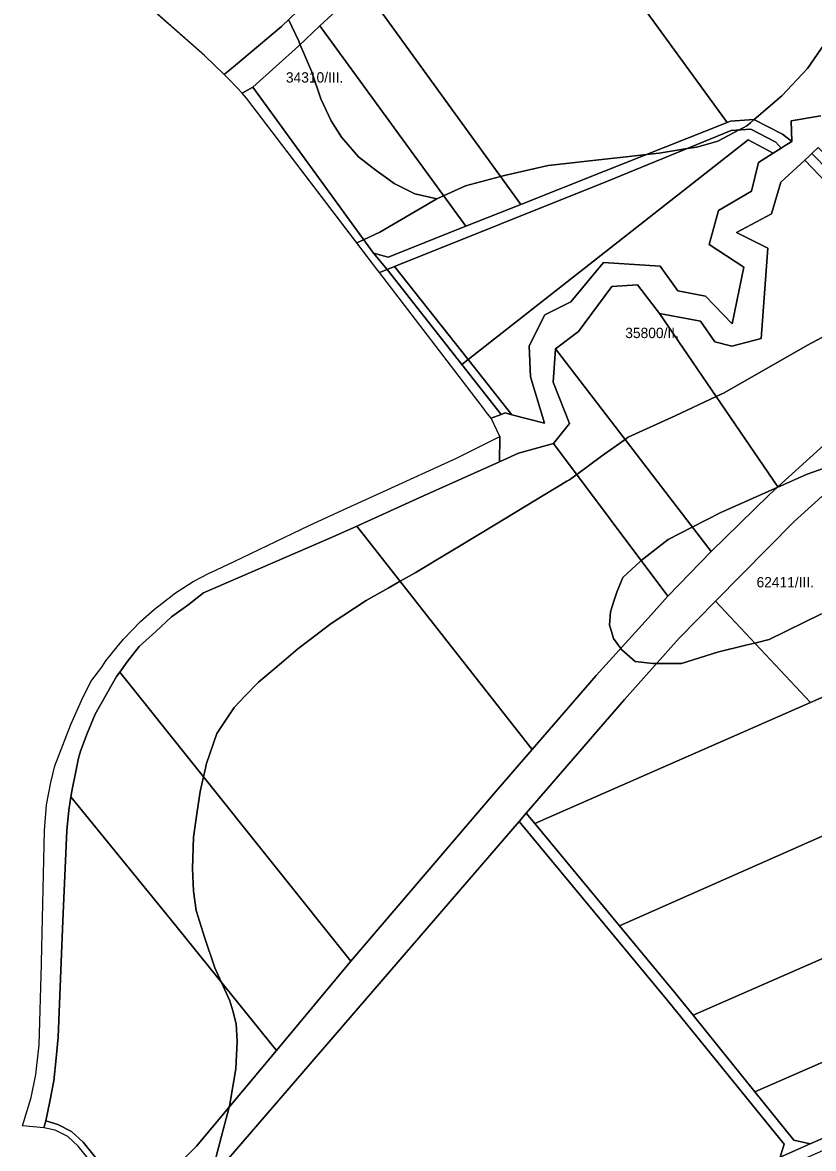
# Model space of a CAD drawing. Extents: x -522079 to -518833, y -1142400 to -1139961.
# Drawn here: x -521980 to -521596, y -1141010 to -1140463 of the extents above; entities that cross this region are included whole.
import ezdxf

# ---------------------------------------------------------------- set-up
doc = ezdxf.new("R2010")
doc.units = 0
for name, color, linetype in [('95560013', 7, 'Continuous'), ('95630013', 7, 'Continuous'), ('95640013', 7, 'Continuous'), ('95660013', 7, 'Continuous')]:
    doc.layers.add(name, color=color, linetype=linetype)

msp = doc.modelspace()

# ---------------------------------------------------------------- linework, layer by layer
at = {"layer": '95560013'}
for points in [[(-521592.51, -1140508.64), (-521606.9, -1140511.13), (-521606.6, -1140521.1), (-521611.18, -1140517.57), (-521625.07, -1140510.37), (-521636.41, -1140511.21), (-521638.02, -1140511.86), (-521742.3, -1140368.5), (-521728.93, -1140357.06), (-521708.67, -1140341.98), (-521697.12, -1140332.11), (-521688.85, -1140323.27), (-521680.22, -1140314.66), (-521674.58, -1140306.67), (-521664.44, -1140291.34), (-521641.46, -1140251.62), (-521633.25, -1140239.25), (-521625.36, -1140230.13), (-521613.09, -1140218.9), (-521610.22, -1140216.5), (-521608.33, -1140219.87), (-521596.95, -1140234.61), (-521579.62, -1140257.92)], [(-521925.13, -1141037.95), (-521895.5, -1141008.4), (-521856.78, -1140962.03), (-521820.63, -1140918.73), (-521750.36, -1140836.58), (-521732.61, -1140815.99), (-521701.61, -1140780.11), (-521674.73, -1140750.53), (-521666.78, -1140741.6), (-521645.77, -1140720.02), (-521617.82, -1140692.69), (-521613.36, -1140688.64), (-521587.52, -1140665.2)], [(-521576.52, -1140679.31), (-521605.53, -1140705.44), (-521643.56, -1140744), (-521661.3, -1140761.99), (-521687.87, -1140791.7), (-521735.53, -1140846.95), (-521738.91, -1140850.87), (-521884.07, -1141019.15)]]:
    msp.add_lwpolyline(points, dxfattribs=at)
for points in [[(-521924.65, -1140450.32), (-521818.63, -1140351.09), (-521781.95, -1140390.97), (-521803.88, -1140414.74), (-521822.79, -1140434.86), (-521839, -1140450.48), (-521854.3, -1140465.27), (-521876.66, -1140484.09), (-521882.18, -1140488.56), (-521891.73, -1140479.43)], [(-521747.91, -1140373.33), (-521742.3, -1140368.5), (-521638.02, -1140511.86), (-521697.45, -1140535.57), (-521738.18, -1140551.68), (-521815.4, -1140444.86), (-521814.39, -1140443.83), (-521794.87, -1140423.48), (-521773.82, -1140399.6), (-521757.78, -1140381.98)], [(-521829.77, -1140459.58), (-521815.4, -1140444.86), (-521738.18, -1140551.68), (-521764.87, -1140562.24), (-521835.62, -1140465.09)], [(-521835.62, -1140465.09), (-521764.87, -1140562.24), (-521802.53, -1140577.14), (-521809.71, -1140575.34), (-521868.24, -1140494.75), (-521845.84, -1140474.71)], [(-521809.71, -1140575.34), (-521803.08, -1140583.22), (-521806.71, -1140584.66), (-521807.95, -1140583.04), (-521871.3, -1140500.06), (-521873.47, -1140497.6), (-521868.24, -1140494.75)], [(-521802.53, -1140577.14), (-521764.87, -1140562.24), (-521738.18, -1140551.68), (-521697.45, -1140535.57), (-521638.02, -1140511.86), (-521636.41, -1140511.21), (-521625.07, -1140510.37), (-521611.18, -1140517.57), (-521606.6, -1140521.1), (-521609.78, -1140523.1), (-521611.69, -1140524.3), (-521614.4, -1140521.49), (-521626.56, -1140515.18), (-521635.99, -1140515.78), (-521696.07, -1140540.42), (-521799.46, -1140581.76), (-521803.08, -1140583.22), (-521809.71, -1140575.34)], [(-521614.4, -1140521.49), (-521611.69, -1140524.3), (-521615.57, -1140526.74), (-521627.73, -1140520.35), (-521763.73, -1140626.86), (-521799.46, -1140581.76), (-521696.07, -1140540.42), (-521635.99, -1140515.78), (-521626.56, -1140515.18)], [(-521646.65, -1140571), (-521629.87, -1140582.04), (-521635.54, -1140609.6), (-521648.43, -1140596.09), (-521661.89, -1140593.5), (-521670.5, -1140581.53), (-521698, -1140579.74), (-521713.89, -1140598.84), (-521726.52, -1140605.2), (-521734.01, -1140620.28), (-521733.38, -1140635.33), (-521726.67, -1140657.74), (-521742.5, -1140653.65), (-521763.73, -1140626.86), (-521627.73, -1140520.35), (-521615.57, -1140526.74), (-521622.75, -1140531.26), (-521626.2, -1140545.21), (-521642.26, -1140554.66)], [(-521521.75, -1140612.22), (-521600.31, -1140530.11), (-521598.04, -1140528.01), (-521596.8, -1140526.87), (-521570.34, -1140553.98), (-521517.85, -1140609.14)], [(-521587.52, -1140665.2), (-521613.36, -1140688.64), (-521670.89, -1140604.59), (-521650.96, -1140608.19), (-521643.99, -1140618.34), (-521635.78, -1140620.38), (-521621.47, -1140616.67), (-521618.3, -1140572.85), (-521633.5, -1140565.29), (-521616.47, -1140556.14), (-521611.96, -1140540.86), (-521600.31, -1140530.11), (-521521.75, -1140612.22), (-521556.8, -1140639.91)], [(-521799.46, -1140581.76), (-521763.73, -1140626.86), (-521766.84, -1140629.25), (-521803.08, -1140583.22)], [(-521806.71, -1140584.66), (-521803.08, -1140583.22), (-521766.84, -1140629.25), (-521747.72, -1140653.54), (-521752.49, -1140655.36), (-521754.23, -1140653.26), (-521756.45, -1140650.36)], [(-521613.36, -1140688.64), (-521617.82, -1140692.69), (-521645.77, -1140720.02), (-521721.28, -1140621.72), (-521710.1, -1140613.29), (-521693.94, -1140591.41), (-521681.44, -1140590.68), (-521670.89, -1140604.59)], [(-521714.47, -1140657.84), (-521722.39, -1140637.91), (-521721.28, -1140621.72), (-521645.77, -1140720.02), (-521666.78, -1140741.6), (-521722.24, -1140667.6)], [(-521424.45, -1140717.21), (-521517.19, -1140758), (-521597.52, -1140793.25), (-521643.56, -1140744), (-521605.53, -1140705.44), (-521576.52, -1140679.31), (-521545.43, -1140654.05), (-521509.24, -1140625.15)], [(-521763.73, -1140626.86), (-521742.5, -1140653.65), (-521745.77, -1140652.8), (-521747.72, -1140653.54), (-521766.84, -1140629.25)], [(-521674.73, -1140750.53), (-521701.61, -1140780.11), (-521732.61, -1140815.99), (-521817.76, -1140707.64), (-521785.36, -1140693.05), (-521748.53, -1140676.5), (-521739.27, -1140672.34), (-521722.24, -1140667.6), (-521666.78, -1140741.6)], [(-521820.63, -1140918.73), (-521932.78, -1140778.46), (-521929.14, -1140773.45), (-521923.36, -1140766.09), (-521915.35, -1140758.73), (-521907.65, -1140751.59), (-521899.73, -1140746), (-521892.09, -1140739.95), (-521829.78, -1140713), (-521817.76, -1140707.64), (-521732.61, -1140815.99), (-521750.36, -1140836.58)], [(-521589.34, -1140856.91), (-521690.16, -1140901.59), (-521731.35, -1140851.98), (-521597.52, -1140793.25), (-521517.19, -1140758), (-521424.45, -1140717.21), (-521383.31, -1140761.88), (-521381.12, -1140763.92), (-521473.38, -1140805.12)], [(-521735.53, -1140846.95), (-521687.87, -1140791.7), (-521661.3, -1140761.99), (-521643.56, -1140744), (-521597.52, -1140793.25), (-521731.35, -1140851.98)], [(-521589.34, -1140856.91), (-521473.38, -1140805.12), (-521381.12, -1140763.92), (-521343.03, -1140805.79), (-521433.97, -1140848.31), (-521555.85, -1140901.74), (-521654.5, -1140944.84), (-521662.84, -1140934.49), (-521690.16, -1140901.59)], [(-521856.78, -1140962.03), (-521908.14, -1140898.33), (-521956.51, -1140838.94), (-521956.06, -1140836.18), (-521953.99, -1140825.94), (-521952.78, -1140820.25), (-521951.85, -1140816.81), (-521948.6, -1140808.27), (-521944.68, -1140798.86), (-521939.28, -1140789.17), (-521934.35, -1140780.63), (-521932.78, -1140778.46), (-521820.63, -1140918.73)], [(-521343.03, -1140805.79), (-521311.05, -1140836.96), (-521307.59, -1140840.17), (-521401.58, -1140884.75), (-521526.28, -1140939.14), (-521624.6, -1140981.98), (-521654.5, -1140944.84), (-521555.85, -1140901.74), (-521433.97, -1140848.31)], [(-521968.74, -1140996.16), (-521966.75, -1140986.81), (-521964.79, -1140976.78), (-521963.61, -1140965.78), (-521962.64, -1140955.52), (-521961.27, -1140919.13), (-521960.41, -1140899.15), (-521958.48, -1140855.25), (-521957.55, -1140845.37), (-521956.51, -1140838.94), (-521908.14, -1140898.33), (-521856.78, -1140962.03), (-521895.5, -1141008.4), (-521925.13, -1141037.95), (-521927.04, -1141035.61), (-521950.59, -1141006.47), (-521956.25, -1141001.25), (-521962.85, -1140997.93)], [(-521526.28, -1140939.14), (-521401.58, -1140884.75), (-521307.59, -1140840.17), (-521288.46, -1140863.02), (-521289.17, -1140869.28), (-521455.15, -1140944.86), (-521597.65, -1141007.23), (-521605.69, -1141005.48), (-521624.6, -1140981.98)], [(-521690.16, -1140901.59), (-521662.84, -1140934.49), (-521654.5, -1140944.84), (-521624.6, -1140981.98), (-521605.69, -1141005.48), (-521597.65, -1141007.23), (-521612.22, -1141013.76), (-521610.31, -1141007.37), (-521666.76, -1140937.87), (-521738.91, -1140850.87), (-521735.53, -1140846.95), (-521731.35, -1140851.98)], [(-521666.76, -1140937.87), (-521610.31, -1141007.37), (-521612.22, -1141013.76), (-521737.51, -1141069.87), (-521813.35, -1141102.46), (-521884.07, -1141019.15), (-521738.91, -1140850.87)], [(-521288.46, -1140863.02), (-521283.24, -1140866.3), (-521272.67, -1140872.95), (-521285.04, -1140873.12), (-521453.3, -1140949.4), (-521594.31, -1141011.83), (-521607.81, -1141017.81), (-521735.67, -1141074.42), (-521844.44, -1141121.41), (-521845.59, -1141127.96), (-521855.85, -1141115.33), (-521847.83, -1141117.27), (-521813.35, -1141102.46), (-521737.51, -1141069.87), (-521612.22, -1141013.76), (-521597.65, -1141007.23), (-521455.15, -1140944.86), (-521289.17, -1140869.28)]]:
    msp.add_lwpolyline(points, close=True, dxfattribs=at)
at = {"layer": '95630013'}
for points in [[(-521593.79, -1140524.1), (-521596.8, -1140526.87), (-521598.04, -1140528.01), (-521600.31, -1140530.11), (-521611.96, -1140540.86), (-521616.47, -1140556.14), (-521633.5, -1140565.29), (-521618.3, -1140572.85), (-521621.47, -1140616.67), (-521635.78, -1140620.38), (-521643.99, -1140618.34), (-521650.96, -1140608.19), (-521670.89, -1140604.59), (-521681.44, -1140590.68), (-521693.94, -1140591.41), (-521710.1, -1140613.29), (-521721.28, -1140621.72), (-521722.39, -1140637.91), (-521714.47, -1140657.84), (-521722.24, -1140667.6), (-521739.27, -1140672.34), (-521748.53, -1140676.5), (-521748.38, -1140664.24), (-521752.49, -1140655.36), (-521747.72, -1140653.54), (-521745.77, -1140652.8), (-521742.5, -1140653.65), (-521726.67, -1140657.74), (-521733.38, -1140635.33), (-521734.01, -1140620.28), (-521726.52, -1140605.2), (-521713.89, -1140598.84), (-521698, -1140579.74), (-521670.5, -1140581.53), (-521661.89, -1140593.5), (-521648.43, -1140596.09), (-521635.54, -1140609.6), (-521629.87, -1140582.04), (-521646.65, -1140571), (-521642.26, -1140554.66), (-521626.2, -1140545.21), (-521622.75, -1140531.26), (-521615.57, -1140526.74), (-521611.69, -1140524.3), (-521609.78, -1140523.1), (-521606.6, -1140521.1), (-521606.9, -1140511.13), (-521592.51, -1140508.64)], [(-521929.14, -1141037.67), (-521952.92, -1141008.37), (-521958.05, -1141003.66), (-521964.16, -1141000.63), (-521969.71, -1140999.55), (-521968.74, -1140996.16), (-521962.85, -1140997.93), (-521956.25, -1141001.25), (-521950.59, -1141006.47), (-521927.04, -1141035.61)]]:
    msp.add_lwpolyline(points, dxfattribs=at)
for points in [[(-521513.48, -1140605.69), (-521517.85, -1140609.14), (-521570.34, -1140553.98), (-521596.8, -1140526.87), (-521593.79, -1140524.1), (-521584.91, -1140532.83), (-521566.82, -1140550.59)], [(-521968.74, -1140996.16), (-521969.71, -1140999.55), (-521980.02, -1140998.54), (-521975.77, -1140984.83), (-521973.56, -1140973.69), (-521972.01, -1140959.19), (-521970.73, -1140920.13), (-521970.78, -1140919.37), (-521969.35, -1140855.23), (-521968.4, -1140842.82), (-521966.23, -1140832.06), (-521964.35, -1140823.92), (-521960.5, -1140813.97), (-521956.64, -1140803.89), (-521951.34, -1140792.2), (-521946.81, -1140782.96), (-521941.53, -1140776.07), (-521939.58, -1140773.02), (-521933.99, -1140766.2), (-521930.99, -1140762.54), (-521922.69, -1140753.87), (-521915.99, -1140747.92), (-521907.36, -1140741.3), (-521906.16, -1140740.38), (-521897.11, -1140734.61), (-521889.34, -1140730.49), (-521885.86, -1140728.85), (-521877.29, -1140724.81), (-521840.82, -1140707.39), (-521822.52, -1140699.01), (-521804.78, -1140690.88), (-521769.34, -1140674.65), (-521748.38, -1140664.24), (-521748.53, -1140676.5), (-521785.36, -1140693.05), (-521817.76, -1140707.64), (-521829.78, -1140713), (-521892.09, -1140739.95), (-521899.73, -1140746), (-521907.65, -1140751.59), (-521915.35, -1140758.73), (-521923.36, -1140766.09), (-521929.14, -1140773.45), (-521932.78, -1140778.46), (-521934.35, -1140780.63), (-521939.28, -1140789.17), (-521944.68, -1140798.86), (-521948.6, -1140808.27), (-521951.85, -1140816.81), (-521952.78, -1140820.25), (-521953.99, -1140825.94), (-521956.06, -1140836.18), (-521956.51, -1140838.94), (-521957.55, -1140845.37), (-521958.48, -1140855.25), (-521960.41, -1140899.15), (-521961.27, -1140919.13), (-521962.64, -1140955.52), (-521963.61, -1140965.78), (-521964.79, -1140976.78), (-521966.75, -1140986.81)]]:
    msp.add_lwpolyline(points, close=True, dxfattribs=at)
at = {"layer": '95640013'}
msp.add_lwpolyline([(-521829.77, -1140459.58), (-521835.62, -1140465.09), (-521845.84, -1140474.71), (-521868.24, -1140494.75), (-521873.47, -1140497.6), (-521875.9, -1140495.08), (-521879.74, -1140491.09), (-521882.18, -1140488.56), (-521876.66, -1140484.09), (-521854.3, -1140465.27), (-521839, -1140450.48)], dxfattribs=at)
at = {"layer": '95660013'}
for points in [[(-521850.83, -1140461.92), (-521845.96, -1140472.52), (-521845.26, -1140474.16), (-521843.12, -1140479.15), (-521839.74, -1140487.06), (-521835.19, -1140500.35), (-521830.22, -1140511.15), (-521825.25, -1140519.04), (-521816.97, -1140528.6), (-521808.28, -1140535.24), (-521802.62, -1140539.29), (-521799.58, -1140541.47), (-521789.65, -1140546.45), (-521778.88, -1140548.95), (-521806.62, -1140565.15), (-521814.45, -1140568.81), (-521817.66, -1140570.32), (-521871.3, -1140500.06), (-521873.47, -1140497.6), (-521875.9, -1140495.08), (-521879.74, -1140491.09), (-521882.18, -1140488.56), (-521891.73, -1140479.43), (-521924.23, -1140450.69)], [(-521589.25, -1140471.59), (-521598.91, -1140485.69), (-521611.51, -1140498.91), (-521624.87, -1140510.47), (-521626.68, -1140512.03), (-521628.5, -1140513.6), (-521630.26, -1140514.52), (-521632.2, -1140515.54), (-521642.55, -1140520.95), (-521651.63, -1140523.59), (-521652.89, -1140523.8), (-521657.38, -1140524.55), (-521670.97, -1140526.82), (-521677.18, -1140527.48), (-521687.01, -1140528.53), (-521695.86, -1140529.47), (-521724.86, -1140532.7), (-521745.36, -1140537.4), (-521747.99, -1140538.11), (-521764.98, -1140542.69), (-521775.62, -1140547.48), (-521778.88, -1140548.95), (-521789.65, -1140546.45), (-521799.58, -1140541.47), (-521802.62, -1140539.29), (-521808.28, -1140535.24), (-521816.97, -1140528.6), (-521825.25, -1140519.04), (-521830.22, -1140511.15), (-521835.19, -1140500.35), (-521839.74, -1140487.06), (-521843.12, -1140479.15), (-521845.26, -1140474.16), (-521845.96, -1140472.52), (-521850.83, -1140461.92)], [(-521929.14, -1141037.67), (-521952.92, -1141008.37), (-521958.05, -1141003.66), (-521964.16, -1141000.63), (-521969.71, -1140999.55), (-521980.02, -1140998.54), (-521975.77, -1140984.83), (-521973.56, -1140973.69), (-521972.01, -1140959.19), (-521970.73, -1140920.13), (-521970.78, -1140919.37), (-521969.35, -1140855.23), (-521968.4, -1140842.82), (-521966.23, -1140832.06), (-521964.35, -1140823.92), (-521960.5, -1140813.97), (-521956.64, -1140803.89), (-521951.34, -1140792.2), (-521946.81, -1140782.96), (-521941.53, -1140776.07), (-521939.58, -1140773.02), (-521933.99, -1140766.2), (-521930.99, -1140762.54), (-521922.69, -1140753.87), (-521915.99, -1140747.92), (-521907.36, -1140741.3), (-521906.16, -1140740.38), (-521897.11, -1140734.61), (-521889.34, -1140730.49), (-521885.86, -1140728.85), (-521877.29, -1140724.81), (-521840.82, -1140707.39), (-521822.52, -1140699.01), (-521804.78, -1140690.88), (-521769.34, -1140674.65), (-521748.38, -1140664.24), (-521752.49, -1140655.36), (-521754.23, -1140653.26), (-521756.45, -1140650.36), (-521806.71, -1140584.66), (-521807.95, -1140583.04), (-521817.66, -1140570.32), (-521814.45, -1140568.81), (-521806.62, -1140565.15), (-521778.88, -1140548.95), (-521775.62, -1140547.48), (-521764.98, -1140542.69), (-521747.99, -1140538.11), (-521745.36, -1140537.4), (-521724.86, -1140532.7), (-521695.86, -1140529.47), (-521687.01, -1140528.53), (-521677.18, -1140527.48), (-521670.97, -1140526.82), (-521657.38, -1140524.55), (-521652.89, -1140523.8), (-521651.63, -1140523.59), (-521642.55, -1140520.95), (-521632.2, -1140515.54), (-521630.26, -1140514.52), (-521628.5, -1140513.6), (-521626.68, -1140512.03), (-521624.87, -1140510.47), (-521611.51, -1140498.91), (-521598.91, -1140485.69), (-521589.25, -1140471.59)], [(-521575.67, -1140607.49), (-521598.95, -1140619.93), (-521639.43, -1140643.03), (-521641.26, -1140643.88), (-521643.33, -1140644.85), (-521663.22, -1140654.19), (-521685.99, -1140664.6), (-521687.51, -1140665.68), (-521698.9, -1140673.74), (-521711, -1140682.59), (-521713.82, -1140684.66), (-521714.9, -1140685.31), (-521715.85, -1140685.88), (-521756.08, -1140710.29), (-521789.48, -1140730.34), (-521796.7, -1140734.43), (-521802.6, -1140737.76), (-521813.26, -1140743.79), (-521830.22, -1140754.96), (-521841.02, -1140763.09), (-521846.41, -1140767.15), (-521854.34, -1140773.94), (-521865.39, -1140783.39), (-521872.05, -1140790.21), (-521877.28, -1140795.58), (-521885.63, -1140808.26), (-521890.69, -1140822.73), (-521890.84, -1140823.43), (-521891.19, -1140825.02), (-521892.14, -1140829.28), (-521893.73, -1140836.44), (-521895.32, -1140847.16), (-521897.01, -1140858.52), (-521897.52, -1140873.75), (-521897.01, -1140884.67), (-521895.75, -1140894.06), (-521891.7, -1140907), (-521886.64, -1140921.98), (-521883.43, -1140928.98), (-521879.3, -1140937.97), (-521877.98, -1140942.83), (-521876.27, -1140949.14), (-521875.76, -1140957.51), (-521876.52, -1140970.97), (-521879.3, -1140987.98), (-521879.69, -1140989.47), (-521883.38, -1141003.58), (-521886.14, -1141014.12)], [(-521886.14, -1141014.12), (-521883.38, -1141003.58), (-521879.69, -1140989.47), (-521879.3, -1140987.98), (-521876.52, -1140970.97), (-521875.76, -1140957.51), (-521876.27, -1140949.14), (-521877.98, -1140942.83), (-521879.3, -1140937.97), (-521883.43, -1140928.98), (-521886.64, -1140921.98), (-521891.7, -1140907), (-521895.75, -1140894.06), (-521897.01, -1140884.67), (-521897.52, -1140873.75), (-521897.01, -1140858.52), (-521895.32, -1140847.16), (-521893.73, -1140836.44), (-521892.14, -1140829.28), (-521891.19, -1140825.02), (-521890.84, -1140823.43), (-521890.69, -1140822.73), (-521885.63, -1140808.26), (-521877.28, -1140795.58), (-521872.05, -1140790.21), (-521865.39, -1140783.39), (-521854.34, -1140773.94), (-521846.41, -1140767.15), (-521841.02, -1140763.09), (-521830.22, -1140754.96), (-521813.26, -1140743.79), (-521802.6, -1140737.76), (-521796.7, -1140734.43), (-521789.48, -1140730.34), (-521756.08, -1140710.29), (-521715.85, -1140685.88), (-521714.9, -1140685.31), (-521713.82, -1140684.66), (-521711, -1140682.59), (-521698.9, -1140673.74), (-521687.51, -1140665.68), (-521685.99, -1140664.6), (-521663.22, -1140654.19), (-521643.33, -1140644.85), (-521641.26, -1140643.88), (-521639.43, -1140643.03), (-521598.95, -1140619.93), (-521575.67, -1140607.49)], [(-521592.12, -1140750.19), (-521617.61, -1140762.73), (-521624.5, -1140764.38), (-521628.89, -1140765.44), (-521642.6, -1140768.75), (-521660.09, -1140774.26), (-521672.27, -1140774.26), (-521674.08, -1140774.26), (-521682.58, -1140773.26), (-521689.08, -1140767.74), (-521689.65, -1140766.95), (-521693.08, -1140762.23), (-521694.13, -1140758.78), (-521695.07, -1140755.71), (-521694.57, -1140749.19), (-521692.81, -1140743.59), (-521691.58, -1140739.67), (-521688.58, -1140732.65), (-521680.08, -1140724.62), (-521679.71, -1140724.34), (-521666.59, -1140714.1), (-521654.91, -1140708.12), (-521641.1, -1140701.06), (-521613.72, -1140688.96), (-521599.12, -1140682.51), (-521566.13, -1140670.87)], [(-521566.13, -1140670.87), (-521599.12, -1140682.51), (-521613.72, -1140688.96), (-521641.1, -1140701.06), (-521654.91, -1140708.12), (-521666.59, -1140714.1), (-521679.71, -1140724.34), (-521680.08, -1140724.62), (-521688.58, -1140732.65), (-521691.58, -1140739.67), (-521692.81, -1140743.59), (-521694.57, -1140749.19), (-521695.07, -1140755.71), (-521694.13, -1140758.78), (-521693.08, -1140762.23), (-521689.65, -1140766.95), (-521689.08, -1140767.74), (-521682.58, -1140773.26), (-521674.08, -1140774.26), (-521672.27, -1140774.26), (-521660.09, -1140774.26), (-521642.6, -1140768.75), (-521628.89, -1140765.44), (-521624.5, -1140764.38), (-521617.61, -1140762.73), (-521592.12, -1140750.19)]]:
    msp.add_lwpolyline(points, dxfattribs=at)

# ---------------------------------------------------------------- texts
for s, rotation, p in [('34310/III.', 0, (-521852.16, -1140492.53)), ('35800/II.', 0, (-521687.43, -1140616.47)), ('62411/III.', 360, (-521623.72, -1140737.38))]:
    msp.add_text(s, height=5, rotation=rotation, dxfattribs=at).set_placement(p)

doc.saveas('drawing.dxf')
